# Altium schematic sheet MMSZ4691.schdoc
size 127 x 101 mm
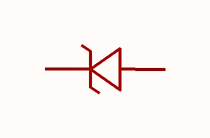
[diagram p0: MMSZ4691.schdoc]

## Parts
U?  mmsz4691  [SOD-123_L2.7-W1.6-LS3.7-RD]  (value not drawn)

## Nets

Not connected (* = marked no-connect by the designer): U? 1(C) 2(A)

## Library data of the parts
U? = mmsz4691: 二极管配置:1个独立式;稳压值(标称值):6.2V;稳压值(范围):5.89V~6.51V;耗散功率(Pd):350mW;; Manufacturer: CJ(江苏长电/长晶); AddInBom: yes; ModelId: ad7e39f9e5534b3c96ffdc5532ebb493; ModelName: SOD-123_L2.7-W1.6-H1.4-LS3.7; ModelTransform: 146.026,62.992,0,180,0,0,0.0005,0,0; Diode Configuration: 1个独立式; Zener Voltage(Nom): 6.2V; Reverse Leakage Current (Ir): 10uA@5V; Pd - Power Dissipation: 350mW; Operating Junction Temperature Range: -55℃~+150℃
